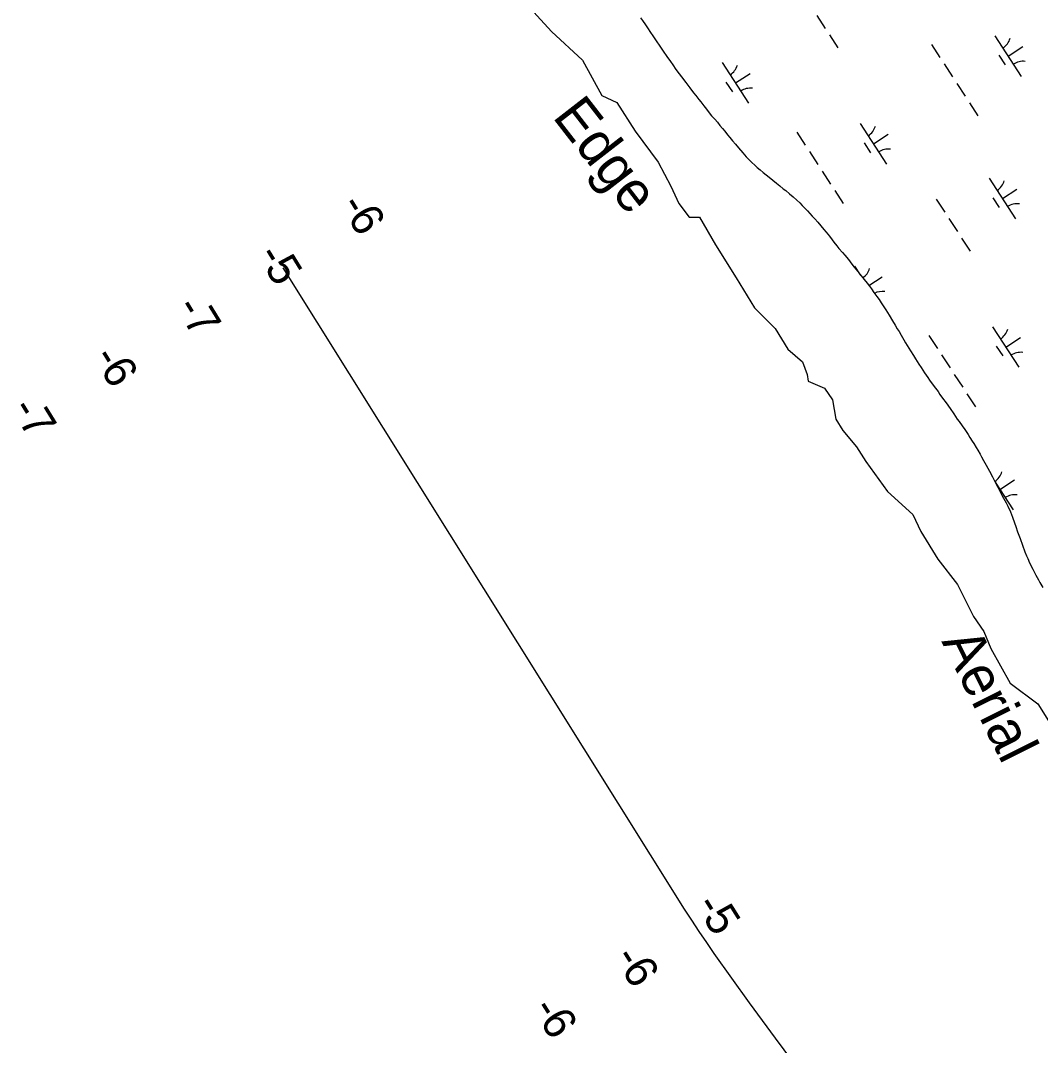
# Model space of a CAD drawing. Extents: x 3953924 to 3974542, y 193747 to 216192.
# Drawn here: x 3963374 to 3964429, y 204501 to 205562 of the extents above; entities that cross this region are included whole.
import ezdxf

# ---------------------------------------------------------------- set-up
doc = ezdxf.new("R2010")
doc.units = 0
for name, color, linetype in [('V-RIVR-EDGE', 7, 'Continuous'), ('V-RIVR-IDEN', 7, 'Continuous'), ('V-RIVR-RANG', 7, 'Continuous'), ('V-TOPO-MINR', 7, 'Continuous'), ('V-WETL-SWMP', 7, 'Continuous')]:
    doc.layers.add(name, color=color, linetype=linetype)

msp = doc.modelspace()

# ---------------------------------------------------------------- linework, layer by layer
at = {"layer": 'V-RIVR-EDGE'}
msp.add_lwpolyline([(3963893.4, 205582.7), (3963923.1, 205550.6), (3963955.2, 205520.9), (3963975.3, 205484.1), (3963990.8, 205477), (3964009.8, 205447.3), (3964033.5, 205415.3), (3964046.6, 205390.3), (3964054.9, 205372.5), (3964065.6, 205358.3), (3964076.3, 205358.3), (3964092.9, 205329.8), (3964114.3, 205295.4), (3964133.2, 205264.5), (3964154.6, 205243.1), (3964167.7, 205221.7), (3964183.1, 205208.7), (3964187.9, 205195.6), (3964189, 205188.5), (3964205.7, 205181.4), (3964214, 205169.5), (3964217.5, 205149.3), (3964224.7, 205137.5), (3964238.9, 205120.8), (3964248.4, 205105.4), (3964271, 205074.5), (3964297.1, 205050.8), (3964305.4, 205033), (3964323.2, 205004.5), (3964343.4, 204978.4), (3964360, 204945.1), (3964370.7, 204929.7), (3964377.8, 204911.9), (3964398, 204876.3), (3964426.5, 204854.9), (3964447.9, 204820.5)], dxfattribs=at)
at = {"layer": 'V-TOPO-MINR'}
msp.add_lwpolyline([(3964182.1, 204472.6), (3964154.9, 204508.8), (3964128.2, 204545.3), (3964091.7, 204596.6), (3964083.8, 204607.9), (3964076, 204619.3), (3964068.5, 204630.8), (3964061, 204642.4), (3963645.3, 205305.9)], dxfattribs=at)
at = {"layer": 'V-WETL-SWMP'}
for p, q in [((3964015.2, 205564.6), (3964017.4, 205561.7)), ((3964197.7, 205567.1), (3964206.4, 205553.7)), ((3964017.4, 205561.7), (3964020.4, 205557.3)), ((3964020.4, 205557.3), (3964022.6, 205554.2)), ((3964022.6, 205554.2), (3964025.7, 205549.4)), ((3964025.7, 205549.4), (3964028.1, 205546)), ((3964028.1, 205546), (3964031.5, 205540.7)), ((3964210.8, 205547), (3964219.5, 205533.6)), ((3964382.2, 205545.9), (3964409.5, 205504)), ((3964031.5, 205540.7), (3964035.3, 205535.3)), ((3964035.3, 205535.3), (3964038.9, 205530)), ((3964316.4, 205537), (3964325.1, 205523.6)), ((3964395.9, 205525), (3964410.9, 205534.8)), ((3964038.9, 205530), (3964042.7, 205524.6)), ((3964042.7, 205524.6), (3964046.4, 205519.4)), ((3964386.1, 205525.8), (3964392.7, 205515.8)), ((3964046.4, 205519.4), (3964048.8, 205516.1)), ((3964048.8, 205516.1), (3964052, 205511.2)), ((3964052, 205511.2), (3964055.4, 205506.5)), ((3964099.9, 205518.2), (3964127.2, 205476.3)), ((3964329.5, 205516.9), (3964338.2, 205503.5)), ((3964055.4, 205506.5), (3964057.6, 205503.7)), ((3964057.6, 205503.7), (3964062.2, 205497.7)), ((3964113.6, 205497.2), (3964128.7, 205507)), ((3964062.2, 205497.7), (3964064.4, 205494.8)), ((3964064.4, 205494.8), (3964066.5, 205492.1)), ((3964066.5, 205492.1), (3964070.3, 205487)), ((3964103.8, 205498), (3964110.4, 205488)), ((3964342.6, 205496.8), (3964351.3, 205483.4)), ((3964070.3, 205487), (3964072.7, 205484.1)), ((3964072.7, 205484.1), (3964075.7, 205480.2)), ((3964075.7, 205480.2), (3964077.7, 205477.5)), ((3964077.7, 205477.5), (3964080.8, 205473.5)), ((3964080.8, 205473.5), (3964083.5, 205470.1)), ((3964083.5, 205470.1), (3964086.4, 205466.4)), ((3964355.7, 205476.7), (3964364.4, 205463.3)), ((3964086.4, 205466.4), (3964088.8, 205463.3)), ((3964088.8, 205463.3), (3964092.1, 205459.6)), ((3964092.1, 205459.6), (3964094.9, 205456.5)), ((3964094.9, 205456.5), (3964097.5, 205453.3)), ((3964097.5, 205453.3), (3964100.2, 205450.2)), ((3964100.2, 205450.2), (3964102.5, 205447.4)), ((3964102.5, 205447.4), (3964105.5, 205443.6)), ((3964177, 205446.3), (3964185.7, 205432.9)), ((3964242.8, 205455.2), (3964270.1, 205413.3)), ((3964105.5, 205443.6), (3964107.8, 205440.7)), ((3964107.8, 205440.7), (3964110.5, 205437.3)), ((3964110.5, 205437.3), (3964113.6, 205433.8)), ((3964246.7, 205435.1), (3964253.3, 205425)), ((3964256.5, 205434.2), (3964271.5, 205444.1)), ((3964113.6, 205433.8), (3964116.8, 205430)), ((3964116.8, 205430), (3964121.1, 205424.9)), ((3964121.1, 205424.9), (3964124.7, 205420.9)), ((3964190.1, 205426.2), (3964198.8, 205412.7)), ((3964124.7, 205420.9), (3964130.6, 205414.9)), ((3964130.6, 205414.9), (3964133.5, 205412.2)), ((3964133.5, 205412.2), (3964136.2, 205409.8)), ((3964136.2, 205409.8), (3964139.2, 205407.3)), ((3964139.2, 205407.3), (3964142.4, 205404.6)), ((3964142.4, 205404.6), (3964145.3, 205402.3)), ((3964203.2, 205406), (3964211.9, 205392.6)), ((3964145.3, 205402.3), (3964148.5, 205399.6)), ((3964148.5, 205399.6), (3964152.3, 205396.7)), ((3964152.3, 205396.7), (3964156, 205393.6)), ((3964156, 205393.6), (3964159.4, 205390.8)), ((3964376.2, 205398.6), (3964403.5, 205356.7)), ((3964159.4, 205390.8), (3964163, 205387.8)), ((3964163, 205387.8), (3964165.6, 205385.8)), ((3964165.6, 205385.8), (3964169.6, 205382.4)), ((3964169.6, 205382.4), (3964173.3, 205379.3)), ((3964216.3, 205385.9), (3964225, 205372.5)), ((3964389.9, 205377.6), (3964405, 205387.4)), ((3964173.3, 205379.3), (3964177, 205376)), ((3964177, 205376), (3964180.1, 205373)), ((3964180.1, 205373), (3964182.5, 205370.5)), ((3964321.5, 205376.9), (3964330.2, 205363.5)), ((3964380.1, 205378.4), (3964386.7, 205368.4)), ((3964182.5, 205370.5), (3964185.1, 205367.9)), ((3964185.1, 205367.9), (3964188.2, 205364.9)), ((3964188.2, 205364.9), (3964190.5, 205362.3)), ((3964190.5, 205362.3), (3964193.1, 205359.5)), ((3964193.1, 205359.5), (3964195.8, 205356.5)), ((3964195.8, 205356.5), (3964198.7, 205353.1)), ((3964198.7, 205353.1), (3964202, 205349.4)), ((3964334.6, 205356.8), (3964343.3, 205343.4)), ((3964202, 205349.4), (3964205.1, 205345.5)), ((3964205.1, 205345.5), (3964207.4, 205342.7)), ((3964207.4, 205342.7), (3964210.8, 205338.6)), ((3964210.8, 205338.6), (3964213.6, 205335)), ((3964213.6, 205335), (3964215.5, 205332.5)), ((3964215.5, 205332.5), (3964218.6, 205328.7)), ((3964347.7, 205336.7), (3964356.4, 205323.3)), ((3964218.6, 205328.7), (3964220.6, 205326)), ((3964220.6, 205326), (3964224.3, 205321.9)), ((3964224.3, 205321.9), (3964226.8, 205319)), ((3964226.8, 205319), (3964230.5, 205314.4)), ((3964230.5, 205314.4), (3964234, 205309.8)), ((3964234, 205309.8), (3964236.4, 205306.6)), ((3964236.8, 205307.8), (3964242.8, 205298.6)), ((3964236.4, 205306.6), (3964240.1, 205302.2)), ((3964240.1, 205302.2), (3964242.3, 205299.2)), ((3964242.3, 205299.2), (3964246.9, 205293.8)), ((3964246.9, 205293.8), (3964250, 205289.9)), ((3964250, 205289.9), (3964252.3, 205287)), ((3964251.7, 205287.7), (3964265.6, 205296.7)), ((3964252.3, 205287), (3964254.3, 205284.1)), ((3964254.3, 205284.1), (3964256.8, 205280.5)), ((3964256.8, 205280.5), (3964260.1, 205276.2)), ((3964260.1, 205276.2), (3964262.2, 205273)), ((3964262.2, 205273), (3964264.4, 205269.6)), ((3964264.4, 205269.6), (3964267.3, 205265.5)), ((3964267.3, 205265.5), (3964269.2, 205262.6)), ((3964269.2, 205262.6), (3964272.6, 205257.1)), ((3964272.6, 205257.1), (3964276, 205251.2)), ((3964276, 205251.2), (3964279, 205246.5)), ((3964279, 205246.5), (3964281.1, 205242.8)), ((3964379.7, 205244.9), (3964407, 205203)), ((3964281.1, 205242.8), (3964282.9, 205240)), ((3964282.9, 205240), (3964285.1, 205236.1)), ((3964285.1, 205236.1), (3964287.8, 205231.5)), ((3964313.9, 205235.9), (3964322.6, 205222.5)), ((3964393.4, 205223.9), (3964408.5, 205233.7)), ((3964287.8, 205231.5), (3964289.7, 205228.4)), ((3964289.7, 205228.4), (3964294.7, 205220.2)), ((3964383.6, 205224.7), (3964390.2, 205214.7)), ((3964294.7, 205220.2), (3964297.9, 205215.1)), ((3964297.9, 205215.1), (3964300, 205211.6)), ((3964327, 205215.8), (3964335.7, 205202.4)), ((3964300, 205211.6), (3964303.3, 205206.4)), ((3964303.3, 205206.4), (3964305.7, 205202.7)), ((3964305.7, 205202.7), (3964309.2, 205197.4)), ((3964309.2, 205197.4), (3964312.7, 205192.4)), ((3964312.7, 205192.4), (3964314.6, 205189.6)), ((3964340.1, 205195.7), (3964348.8, 205182.3)), ((3964314.6, 205189.6), (3964318.3, 205184.5)), ((3964318.3, 205184.5), (3964320.7, 205181.3)), ((3964320.7, 205181.3), (3964323.4, 205177.9)), ((3964323.4, 205177.9), (3964325.3, 205175)), ((3964325.3, 205175), (3964328, 205171)), ((3964328, 205171), (3964331.6, 205166.1)), ((3964353.2, 205175.6), (3964361.9, 205162.2)), ((3964331.6, 205166.1), (3964335.9, 205160.2)), ((3964335.9, 205160.2), (3964339.8, 205154.7)), ((3964339.8, 205154.7), (3964343.2, 205149.5)), ((3964343.2, 205149.5), (3964345, 205146.8)), ((3964345, 205146.8), (3964348.4, 205142.4)), ((3964348.4, 205142.4), (3964351, 205138.7)), ((3964351, 205138.7), (3964354.4, 205133.6)), ((3964354.4, 205133.6), (3964356.3, 205130.4)), ((3964356.3, 205130.4), (3964358.7, 205126.7)), ((3964358.7, 205126.7), (3964360.3, 205124.2)), ((3964360.3, 205124.2), (3964362.7, 205120.1)), ((3964362.7, 205120.1), (3964364.5, 205117.3)), ((3964364.5, 205117.3), (3964366.9, 205113.2)), ((3964366.9, 205113.2), (3964368.4, 205110.4)), ((3964368.4, 205110.4), (3964370.4, 205106.7)), ((3964370.4, 205106.7), (3964373.2, 205101.6)), ((3964373.2, 205101.6), (3964376.7, 205095.5)), ((3964376.7, 205095.5), (3964379.8, 205089.7)), ((3964379.8, 205089.7), (3964382.5, 205084.1)), ((3964387.4, 205076.6), (3964402.5, 205086.4)), ((3964382.4, 205084.2), (3964401, 205055.6)), ((3964382.5, 205084.1), (3964385.1, 205078.9)), ((3964385.1, 205078.9), (3964388, 205073.3)), ((3964388, 205073.3), (3964389.4, 205070.6)), ((3964389.4, 205070.6), (3964391, 205067.5)), ((3964391, 205067.5), (3964393.7, 205062.7)), ((3964393.7, 205062.7), (3964395.4, 205059.3)), ((3964395.4, 205059.3), (3964398.2, 205053.4)), ((3964398.2, 205053.4), (3964400.4, 205047.8)), ((3964400.4, 205047.8), (3964402.6, 205042.1)), ((3964402.6, 205042.1), (3964403.9, 205038.2)), ((3964403.9, 205038.2), (3964405.7, 205032.8)), ((3964405.7, 205032.8), (3964408.2, 205025.8)), ((3964408.2, 205025.8), (3964410.6, 205018.8)), ((3964410.6, 205018.8), (3964413.2, 205012.1)), ((3964413.2, 205012.1), (3964415, 205007.8)), ((3964415, 205007.8), (3964416.2, 205005)), ((3964416.2, 205005), (3964418, 205000.6)), ((3964418, 205000.6), (3964421.4, 204994.3)), ((3964421.4, 204994.3), (3964424.6, 204987.9)), ((3964424.6, 204987.9), (3964427.1, 204983.2)), ((3964427.1, 204983.2), (3964428.8, 204980.3)), ((3964428.8, 204980.3), (3964431.7, 204975.2))]:
    msp.add_line(p, q, dxfattribs=at)
for centre, start, end in [((3964381, 205548.3), 302.2901, 343.8338), ((3964098.7, 205520.5), 302.2901, 343.8338), ((3964411.1, 205502), 82.2901, 123.8337), ((3964128.8, 205474.2), 82.2901, 123.8337), ((3964241.6, 205457.5), 302.2901, 343.8338), ((3964271.7, 205411.2), 82.2901, 123.8337), ((3964375, 205400.9), 302.2901, 343.8338), ((3964405.1, 205354.6), 82.2901, 123.8337), ((3964235.6, 205310.2), 303.7997, 343.8338), ((3964265.7, 205263.9), 82.2901, 117.5355), ((3964378.5, 205247.2), 302.2901, 343.8338), ((3964408.6, 205200.9), 82.2901, 123.8337), ((3964372.5, 205099.8), 302.6921, 343.8338), ((3964402.7, 205053.5), 82.2901, 123.8337)]:
    msp.add_arc(centre, 17.6, start, end, dxfattribs=at)

# ---------------------------------------------------------------- texts
at = {"layer": 'V-RIVR-IDEN'}
for s, rotation, p in [('Edge', 307.8239, (3963923.4, 205462.1)), ('Aerial', 296.4401, (3964326.6, 204919.4))]:
    msp.add_text(s, height=42, rotation=rotation, dxfattribs=at).set_placement(p)
at = {"layer": 'V-RIVR-RANG'}
for s, rotation, p in [('-6', 301.5941, (3963703.6, 205370.7)), ('-5', 301.5941, (3963617.7, 205318.8)), ('-7', 301.5941, (3963533.5, 205264.9)), ('-6', 301.5941, (3963447.7, 205213.4)), ('-7', 301.5941, (3963363.1, 205160.1)), ('-5', 302.1681, (3964071.2, 204646.3)), ('-6', 302.1681, (3963987, 204592.4)), ('-6', 302.1681, (3963902.4, 204539.2))]:
    msp.add_text(s, height=33.5, rotation=rotation, dxfattribs=at).set_placement(p)

doc.saveas('drawing.dxf')
